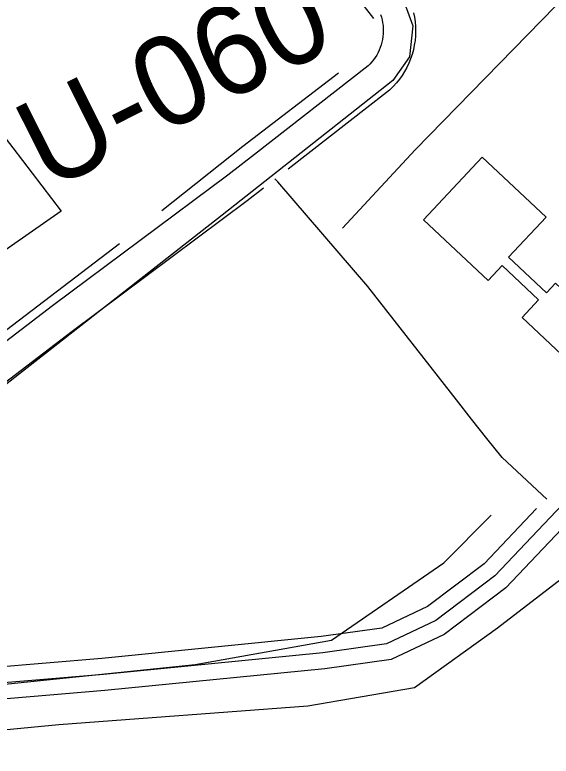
# Model space of a CAD drawing. Extents: x 3405885 to 3443815, y 558517 to 583997.
# Drawn here: x 3413447 to 3413945, y 573242 to 573930 of the extents above; entities that cross this region are included whole.
import ezdxf

# ---------------------------------------------------------------- set-up
doc = ezdxf.new("R2010")
doc.units = 0
for name, color, linetype in [('V-BLDG-OTLN', 7, 'Continuous'), ('V-RIVR-RANG-IDEN', 7, 'Continuous'), ('V-ROAD-CNTR', 7, 'Continuous'), ('V-SITE-OTLN', 7, 'Continuous'), ('V-TOPO-SHOR', 7, 'Continuous'), ('V-UTIL-LINE', 7, 'Continuous')]:
    doc.layers.add(name, color=color, linetype=linetype)

msp = doc.modelspace()

# ---------------------------------------------------------------- linework, layer by layer
at = {"layer": 'V-BLDG-OTLN'}
msp.add_lwpolyline([(3413826.59, 573740.13), (3413881.05, 573798.13), (3413940.43, 573742.37), (3413905.56, 573705.23), (3413940.61, 573672.32), (3413949.06, 573681.33), (3413968.5, 573663.07), (3413975.23, 573670.23), (3413991.9, 573654.57), (3413954.8, 573615.06), (3413918.11, 573649.51), (3413933.31, 573665.7), (3413899.47, 573697.48), (3413886.6, 573683.78)], close=True, dxfattribs=at)
at = {"layer": 'V-ROAD-CNTR'}
for points in [[(3414139.77, 573697.41), (3414069.66, 573596.09), (3413892.83, 573409.72), (3413837.97, 573368.32), (3413792.21, 573346.53), (3413733.23, 573338.44), (3413529.54, 573318.25), (3413219.11, 573292.09), (3412885.01, 573261.82), (3412799.31, 573260.08), (3412715.56, 573266.19), (3412613.74, 573273.61), (3412541.53, 573288.84), (3412479.12, 573305.45), (3412418.8, 573344.44), (3412346.8, 573407.95), (3412242.78, 573531.32), (3412069.67, 573750.99), (3411960.21, 573896.96), (3411844.83, 574046), (3411731.59, 574190.34)], [(3413786.69, 573930.43), (3413787.49, 573927.95), (3413788.15, 573925.43), (3413788.66, 573922.88), (3413789.02, 573920.31), (3413789.22, 573917.71), (3413789.28, 573915.12), (3413789.19, 573912.51), (3413788.94, 573909.93), (3413788.55, 573907.36), (3413788, 573904.81), (3413787.31, 573902.31), (3413786.48, 573899.84), (3413785.5, 573897.43), (3413784.39, 573895.09), (3413783.13, 573892.8), (3413781.76, 573890.6), (3413780.25, 573888.48), (3413778.62, 573886.45), (3413776.88, 573884.52), (3413775.34, 573883.01), (3413669.68, 573800.74)], [(3413817.4, 573932.14), (3413818.25, 573927.88), (3413818.85, 573923.58), (3413819.2, 573919.24), (3413819.29, 573914.9), (3413819.13, 573910.56), (3413818.73, 573906.23), (3413818.06, 573901.93), (3413817.16, 573897.69), (3413816, 573893.5), (3413814.61, 573889.39), (3413812.98, 573885.36), (3413811.11, 573881.43), (3413809.02, 573877.62), (3413806.72, 573873.94), (3413804.2, 573870.39), (3413801.48, 573867), (3413798.57, 573863.78), (3413795.16, 573860.42), (3413700.93, 573787.04)], [(3413669.69, 573800.74), (3413644.89, 573781.44), (3413482.32, 573660.29), (3413390.75, 573590.45)], [(3413941.17, 573480.79), (3413899.64, 573519.52), (3413885.3, 573537.14), (3413871.18, 573554.93), (3413857.25, 573572.88), (3413774.82, 573678.07), (3413691.31, 573775.11), (3413688.68, 573778.04)], [(3413678.04, 573769.22), (3413663.07, 573757.57), (3413500.38, 573636.34), (3413410.85, 573568.06)], [(3414152.1, 573688.87), (3414081.34, 573586.6), (3413902.86, 573398.49), (3413845.79, 573355.43), (3413796.56, 573331.99), (3413734.99, 573323.54), (3413530.91, 573303.31), (3413220.42, 573277.15), (3412885.84, 573246.83), (3412798.91, 573245.07), (3412714.47, 573251.23), (3412611.64, 573258.72), (3412538.05, 573274.24), (3412472.97, 573291.56), (3412449.07, 573307.01)], [(3413931.47, 573472.23), (3413882.8, 573420.94), (3413830.15, 573381.21), (3413787.86, 573361.08), (3413731.47, 573353.34), (3413528.17, 573333.19), (3413217.81, 573307.04), (3412884.18, 573276.81), (3412799.7, 573275.09), (3412716.65, 573281.15), (3412615.84, 573288.5), (3412545.01, 573303.43), (3412485.27, 573319.33), (3412471.17, 573328.45)]]:
    msp.add_lwpolyline(points, dxfattribs=at)
at = {"layer": 'V-SITE-OTLN'}
msp.add_lwpolyline([(3413808.48, 573941.77), (3413816.81, 573919.87), (3413813.65, 573891.29), (3413798.07, 573869.14), (3413639.71, 573744.37), (3413407.11, 573562.49)], dxfattribs=at)
at = {"layer": 'V-TOPO-SHOR'}
msp.add_line((3413659.91, 574084.52), (3413780.13, 573926.63), dxfattribs=at)
for points in [[(3413941.45, 573955.78), (3413948.97, 573938.11), (3413818.87, 573804.79), (3413751.37, 573732.31)], [(3413747.75, 573875.93), (3413659.01, 573807.97), (3413583.74, 573748.29)], [(3413544.57, 573717.66), (3413380.91, 573593.12), (3413374.04, 573583.75), (3413370.62, 573577.52)], [(3412198.55, 573514.45), (3412331.35, 573355.29), (3412414.15, 573306.06), (3412469.39, 573262.23), (3412535.53, 573245.97), (3412667.8, 573218.97), (3412833.07, 573203.11), (3413009.19, 573225.84), (3413488.1, 573271.81), (3413719.31, 573289.25), (3413818.36, 573306.17), (3413895.24, 573361.55), (3414010.52, 573450.11), (3414131.21, 573566.24)], [(3412330.99, 573443.4), (3412424.96, 573355.66), (3412513.33, 573289.94), (3412634.59, 573262.89), (3412805.32, 573258.06), (3412976, 573264.25), (3413168.67, 573281.54), (3413614.53, 573327.38), (3413741.1, 573349.92), (3413845.44, 573421.92), (3413889.31, 573466.15)]]:
    msp.add_lwpolyline(points, dxfattribs=at)
at = {"layer": 'V-UTIL-LINE'}
msp.add_lwpolyline([(3413151.21, 574184.69), (3413280.29, 574020.93), (3413445.55, 573806.88), (3413490.37, 573748.18), (3413414.3, 573695.3)], dxfattribs=at)

# ---------------------------------------------------------------- texts
at = {"layer": 'V-RIVR-RANG-IDEN'}
msp.add_text('U-060', height=83, rotation=26.66452, dxfattribs=at).set_placement((3413478.02, 573766.03))

doc.saveas('drawing.dxf')
